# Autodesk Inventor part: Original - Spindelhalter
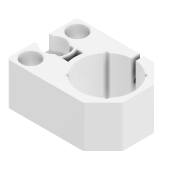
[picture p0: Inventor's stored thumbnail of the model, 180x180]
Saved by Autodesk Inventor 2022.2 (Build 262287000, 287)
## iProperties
Created: 2024-09
Part Number: Original - Spindelhalter
Material: Plastica ABS
Document SubType Name: Modeling
Designer: 18907419
Density: 1.06 g/cm^3
Appearance: Liscia - Bianco
Author: 18907419
Revision Number: ANY
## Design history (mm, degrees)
feature "Schnitt-Linear austragen9"
node "Solido1"
